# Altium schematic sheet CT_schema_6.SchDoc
size 368 x 245 mm
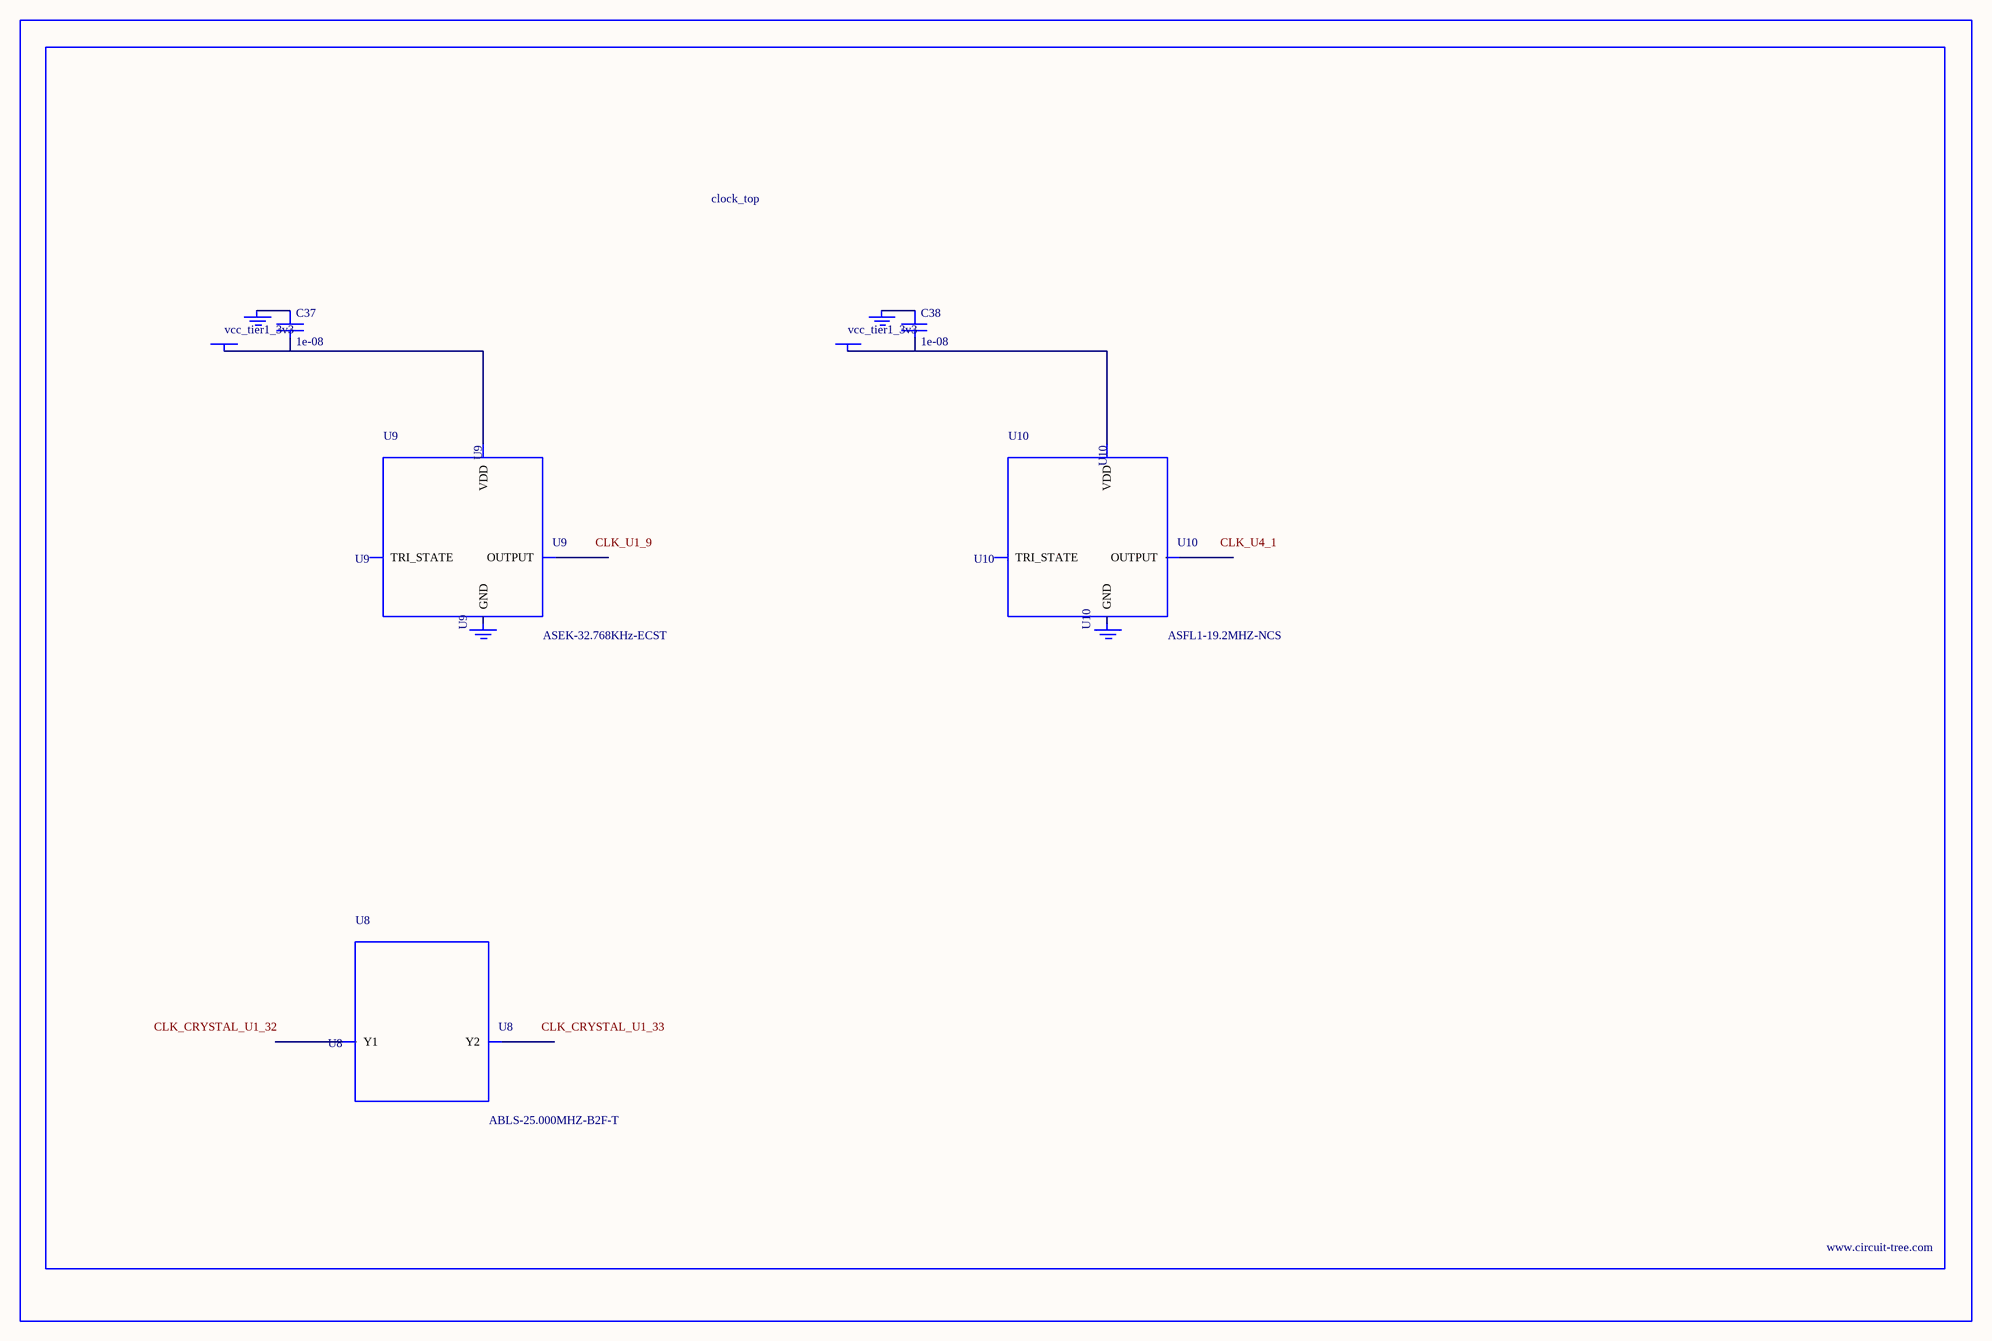
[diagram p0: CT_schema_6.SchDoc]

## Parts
BORDER5  (no value)
C37  1e-08  [C0402]
C38  1e-08  [C0402]
GND_INSTANCE_5_0  (no value)
GND_INSTANCE_5_1  (no value)
GND_INSTANCE_5_2  (no value)
GND_INSTANCE_5_3  (no value)
POWER_INSTANCE_5_0  vcc_tier1_3v3
POWER_INSTANCE_5_1  vcc_tier1_3v3
U8  ABLS-25.000MHZ-B2F-T  [ABLS-25.000MHZ-B2F-T]
U9  ASEK-32.768KHz-ECST  [ASEK]
U10  ASFL1-19.2MHZ-NCS  [ASFL1]

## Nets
NetC37_1: C37.1 GND_INSTANCE_5_0.0(GND)
NetC37_2: C37.2 POWER_INSTANCE_5_0.0(PWR) U9.4(VDD)
NetC38_1: C38.1 GND_INSTANCE_5_2.0(GND)
NetC38_2: C38.2 POWER_INSTANCE_5_1.0(PWR) U10.4(VDD)

Not connected (* = marked no-connect by the designer): GND_INSTANCE_5_1 0(GND); GND_INSTANCE_5_3 0(GND); U8 1(Y1) 2(Y2); U9 1(TRI_STATE) 2(GND) 3(OUTPUT); U10 1(TRI_STATE) 2(GND) 3(OUTPUT)

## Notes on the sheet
- Labels drawn without touching a wire or pin: CLK_CRYSTAL_U1_32, CLK_CRYSTAL_U1_33, CLK_U1_9, CLK_U4_1

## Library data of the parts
BORDER5 = BORDER_PAGE5
C37 C38 = C0402C103K3RAC
GND_INSTANCE_5_0-GND_INSTANCE_5_3 = GND
POWER_INSTANCE_5_0 POWER_INSTANCE_5_1 = PWR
